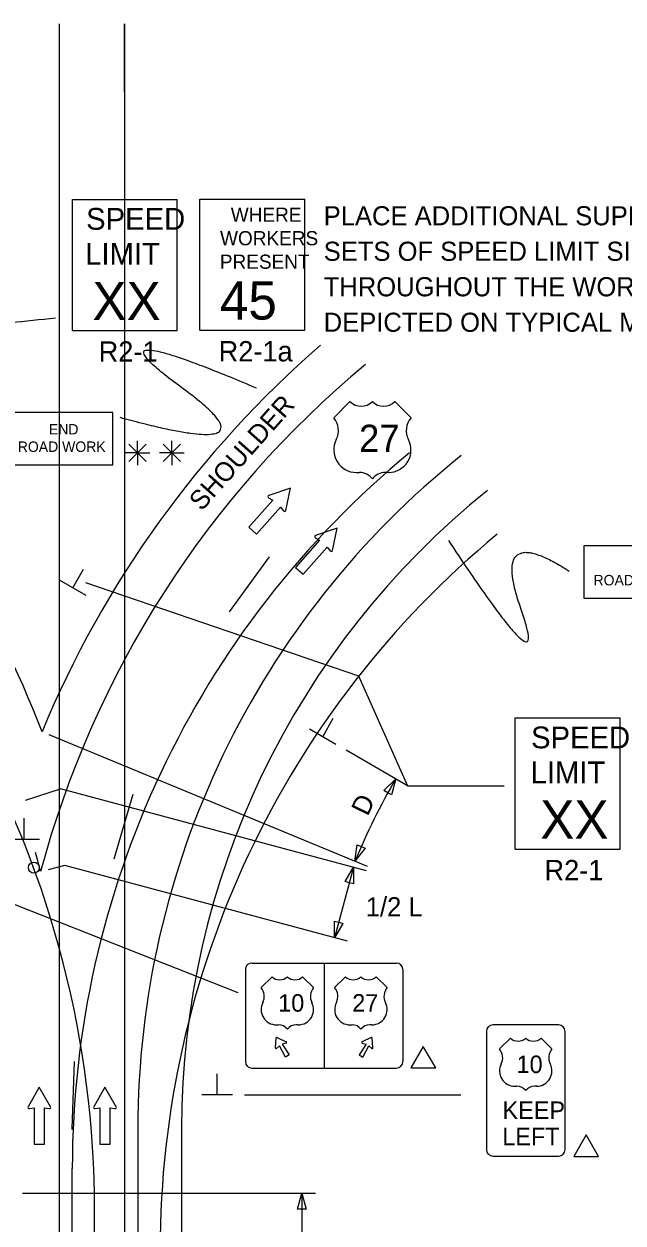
# Model space of a CAD drawing. Extents: x 16731 to 18464, y 5737 to 6974.
# Drawn here: x 16967.8 to 17187.1, y 6535 to 6974.1 of the extents above; entities that cross this region are included whole.
import ezdxf

# ---------------------------------------------------------------- set-up
doc = ezdxf.new("R2010")
doc.units = 0
for name, color, linetype in [('ALI_LEGAL_EX', 7, 'Continuous'), ('MT_SCRATCH_LEVEL_E', 7, 'Continuous'), ('PAVT_EDGE_EX', 7, 'Continuous'), ('TRAFFIC_SIGNS_PR', 7, 'Continuous'), ('TYPICAL_EX', 7, 'Continuous'), ('TYPICAL_TEXT_DIMEN_PR', 7, 'Continuous')]:
    doc.layers.add(name, color=color, linetype=linetype)

msp = doc.modelspace()

# ---------------------------------------------------------------- linework, layer by layer
at = {"layer": 'ALI_LEGAL_EX'}
for p, q in [((16980.68, 6974.12), (16980.68, 6155.98)), ((17004.68, 6974.12), (17004.68, 6155.98)), ((16980.68, 6891.53), (16980.68, 6027.61)), ((17004.68, 6891.53), (17004.68, 6027.61)), ((17007.7, 6691.9), (17000.71, 6668.24)), ((16985.51, 6054.68), (16985.51, 6555.03)), ((16993.65, 6039.29), (16993.65, 6539.64))]:
    msp.add_line(p, q, dxfattribs=at)
for points in [[(17004.68, 6949.12), (17004.68, 6974.12)], [(17043, 6758.79), (17057.75, 6778.98)], [(16985.56, 6569.17), (16985.51, 6569.52), (16986.34, 6594.15)]]:
    msp.add_lwpolyline(points, dxfattribs=at)
for centre, radius, start, end in [((16629.65, 6539.64), 364, 0, 57.2958), ((17325.51, 6555.03), 340, 129.5666, 180), ((17357.65, 6525.15), 340, 129.5666, 180)]:
    msp.add_arc(centre, radius, start, end, dxfattribs=at)
at = {"layer": 'MT_SCRATCH_LEVEL_E'}
for p, q in [((17065.34, 6804.16), (17057.46, 6801.48)), ((17063.63, 6795.99), (17065.34, 6804.16)), ((17058.9, 6799.7), (17050.1, 6789.79)), ((17057.36, 6800.64), (17058.9, 6799.7)), ((17052.89, 6787.3), (17061.7, 6797.21)), ((17061.7, 6797.21), (17062.82, 6795.8)), ((17050.1, 6789.79), (17052.89, 6787.3)), ((17082.42, 6789.5), (17074.54, 6786.82)), ((17080.72, 6781.33), (17082.42, 6789.5)), ((17075.99, 6785.04), (17067.18, 6775.13)), ((17074.45, 6785.99), (17075.99, 6785.04)), ((17069.98, 6772.65), (17078.78, 6782.56)), ((17078.78, 6782.56), (17079.9, 6781.14)), ((17067.18, 6775.13), (17069.98, 6772.65)), ((16973.43, 6584.82), (16969.32, 6577.59)), ((16977.58, 6577.59), (16973.43, 6584.82)), ((16997.48, 6584.82), (16993.37, 6577.59)), ((17001.63, 6577.59), (16997.48, 6584.82)), ((16969.8, 6576.9), (16971.58, 6577.22)), ((16971.58, 6577.22), (16971.58, 6563.96)), ((16975.32, 6563.96), (16975.32, 6577.22)), ((16975.32, 6577.22), (16977.1, 6576.9)), ((16993.85, 6576.9), (16995.63, 6577.22)), ((16995.63, 6577.22), (16995.63, 6563.96)), ((16999.37, 6563.96), (16999.37, 6577.22)), ((16999.37, 6577.22), (17001.15, 6576.9)), ((16971.58, 6563.96), (16975.32, 6563.96)), ((16995.63, 6563.96), (16999.37, 6563.96))]:
    msp.add_line(p, q, dxfattribs=at)
for centre, start, end in [((17057.61, 6801.04), 108.8028, 238.3418), ((17063.18, 6796.09), 218.4141, 348.1511), ((17074.7, 6786.38), 108.8028, 238.3418), ((17080.26, 6781.44), 218.4141, 348.1511), ((16969.73, 6577.36), 150.4248, 279.9638), ((16977.17, 6577.36), 260.0362, 29.7731), ((16993.78, 6577.36), 150.4248, 279.9638), ((17001.22, 6577.36), 260.0362, 29.7731)]:
    msp.add_arc(centre, 0.463, start, end, dxfattribs=at)
at = {"layer": 'PAVT_EDGE_EX'}
for p, q in [((17009.51, 6569.52), (17009.51, 6043.9)), ((17025.51, 6569.52), (17025.51, 6043.9))]:
    msp.add_line(p, q, dxfattribs=at)
for centre, radius, start, end in [((16597.51, 6569.52), 404, 21.0961, 62.1564), ((17325.51, 6569.52), 380, 130.9592, 157.5011), ((17325.51, 6569.52), 364, 129.7293, 165.0045), ((17325.51, 6569.52), 316, 128.7051, 180), ((17325.51, 6569.52), 300, 128.8086, 180), ((16597.51, 6569.52), 388, 14.0482, 15.1223), ((17325.51, 6569.52), 300, 180, 180.00000277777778)]:
    msp.add_arc(centre, radius, start, end, dxfattribs=at)
at = {"layer": 'TRAFFIC_SIGNS_PR'}
for p, q in [((16985.54, 6909.9), (17023.94, 6909.9)), ((16985.54, 6861.9), (16985.54, 6909.9)), ((17023.94, 6861.9), (17023.94, 6909.9)), ((17032.22, 6909.99), (17070.62, 6909.99)), ((17032.22, 6861.99), (17032.22, 6909.99)), ((17070.62, 6861.99), (17070.62, 6909.99)), ((16985.54, 6861.9), (17023.94, 6861.9)), ((17032.22, 6861.99), (17070.62, 6861.99)), ((17147.68, 6719.98), (17186.08, 6719.98)), ((17147.68, 6671.98), (17147.68, 6719.98)), ((17186.08, 6671.98), (17186.08, 6719.98)), ((17147.68, 6671.98), (17186.08, 6671.98)), ((17048.86, 6627.84), (17048.86, 6594.19)), ((17051.26, 6630.24), (17104.13, 6630.24)), ((17077.7, 6630.24), (17077.7, 6591.79)), ((17106.53, 6627.84), (17106.53, 6594.19)), ((17137.08, 6605.16), (17137.08, 6561.91)), ((17163.51, 6607.57), (17139.48, 6607.57)), ((17165.91, 6561.91), (17165.91, 6605.16)), ((17059.85, 6599.15), (17060.14, 6602.78)), ((17060.51, 6602.99), (17063.79, 6601.42)), ((17094.88, 6602.99), (17091.6, 6601.42)), ((17095.54, 6599.15), (17095.25, 6602.78)), ((17051.26, 6591.79), (17104.13, 6591.79)), ((17139.48, 6559.51), (17163.51, 6559.51))]:
    msp.add_line(p, q, dxfattribs=at)
for points in [[(16961.95, 6812.66), (17000.35, 6812.66), (17000.35, 6831.86), (16961.95, 6831.86)], [(17172.71, 6763.79), (17211.11, 6763.79), (17211.11, 6782.99), (17172.71, 6782.99)]]:
    msp.add_lwpolyline(points, close=True, dxfattribs=at)
for points in [[(17063.75, 6600.94), (17062.34, 6600.55), (17064.86, 6596.56), (17063.53, 6595.8), (17061.33, 6599.97), (17060.29, 6598.94)], [(17091.64, 6600.94), (17093.05, 6600.55), (17090.53, 6596.56), (17091.86, 6595.8), (17094.06, 6599.97), (17095.1, 6598.94)]]:
    msp.add_lwpolyline(points, dxfattribs=at)
msp.add_circle((16971.44, 6665.16), 2, dxfattribs=at)
for centre, radius, start, end in [((17051.26, 6627.84), 2.4, 90, 180), ((17051.26, 6627.84), 2.4, 90, 180), ((17104.13, 6627.84), 2.4, 0, 90), ((17139.48, 6605.16), 2.4, 90, 180), ((17163.51, 6605.16), 2.4, 0, 90), ((17060.4, 6602.76), 0.261, 64.4823, 175.5177), ((17063.68, 6601.19), 0.261, 285.9885, 64.4823), ((17091.71, 6601.19), 0.261, 115.5177, 254.0115), ((17094.99, 6602.76), 0.261, 4.4823, 115.5177), ((17060.11, 6599.13), 0.261, 175.5177, 314.0115), ((17095.28, 6599.13), 0.261, 225.9885, 4.4823), ((17051.26, 6594.19), 2.4, 180, 270), ((17104.13, 6594.19), 2.4, 270, 0), ((17139.48, 6561.91), 2.4, 180, 270), ((17163.51, 6561.91), 2.4, 270, 0)]:
    msp.add_arc(centre, radius, start, end, dxfattribs=at)
at = {"layer": 'TYPICAL_EX'}
for p, q in [((17081.21, 6829.94), (17087.1, 6835.84)), ((17109.51, 6829.94), (17103.61, 6835.84)), ((17089.45, 6809.88), (17090.63, 6809.88)), ((17101.26, 6809.88), (17100.08, 6809.88)), ((17054.62, 6621.23), (17058.62, 6625.23)), ((17073.84, 6621.23), (17069.84, 6625.23)), ((17081.55, 6621.23), (17085.55, 6625.23)), ((17100.77, 6621.23), (17096.77, 6625.23)), ((17060.22, 6607.6), (17061.02, 6607.6)), ((17068.24, 6607.6), (17067.44, 6607.6)), ((17087.15, 6607.6), (17087.95, 6607.6)), ((17095.17, 6607.6), (17094.37, 6607.6)), ((17141.88, 6598.76), (17145.89, 6602.76)), ((17161.11, 6598.76), (17157.1, 6602.76)), ((17147.48, 6585.13), (17148.28, 6585.13)), ((17155.5, 6585.13), (17154.7, 6585.13))]:
    msp.add_line(p, q, dxfattribs=at)
for centre, radius, start, end in [((17091.23, 6840.13), 5.96, 226.1404, 313.8596), ((17099.48, 6840.13), 5.96, 226.1404, 313.8596), ((17075.62, 6825.22), 7.31, 333.0977, 40.1936), ((17115.09, 6825.22), 7.31, 139.8064, 206.9023), ((17089.47, 6818.13), 8.24, 152.6698, 269.9013), ((17101.25, 6818.13), 8.24, 270.0987, 27.3302), ((17090.65, 6803.98), 5.91, 37.1038, 90.1385), ((17100.07, 6803.98), 5.91, 89.8615, 142.8962), ((17061.43, 6628.15), 4.05, 226.1404, 313.8596), ((17067.03, 6628.15), 4.05, 226.1404, 313.8596), ((17088.36, 6628.15), 4.05, 226.1404, 313.8596), ((17093.96, 6628.15), 4.05, 226.1404, 313.8596), ((17050.82, 6618.02), 4.97, 333.0977, 40.1936), ((17077.64, 6618.02), 4.97, 139.8064, 206.9023), ((17077.75, 6618.02), 4.97, 333.0977, 40.1936), ((17104.57, 6618.02), 4.97, 139.8064, 206.9023), ((17060.23, 6613.2), 5.6, 152.6698, 269.9013), ((17068.23, 6613.2), 5.6, 270.0987, 27.3302), ((17087.16, 6613.2), 5.6, 152.6698, 269.9013), ((17095.16, 6613.2), 5.6, 270.0987, 27.3302), ((17061.03, 6603.59), 4.01, 37.1038, 90.1385), ((17067.43, 6603.59), 4.01, 89.8615, 142.8962), ((17087.96, 6603.59), 4.01, 37.1038, 90.1385), ((17094.36, 6603.59), 4.01, 89.8615, 142.8962), ((17148.69, 6605.68), 4.05, 226.1404, 313.8596), ((17154.3, 6605.68), 4.05, 226.1404, 313.8596), ((17138.09, 6595.55), 4.97, 333.0977, 40.1936), ((17164.9, 6595.55), 4.97, 139.8064, 206.9023), ((17147.49, 6590.73), 5.6, 152.6698, 269.9013), ((17155.49, 6590.73), 5.6, 270.0987, 27.3302), ((17148.29, 6581.11), 4.01, 37.1038, 90.1385), ((17154.69, 6581.11), 4.01, 89.8615, 142.8962)]:
    msp.add_arc(centre, radius, start, end, dxfattribs=at)
at = {"layer": 'TYPICAL_TEXT_DIMEN_PR'}
for p, q in [((17012.56, 6820.22), (17006.18, 6813.84)), ((17006.19, 6820.22), (17012.56, 6813.84)), ((17009.37, 6817.03), (17009.37, 6821.49)), ((17018.74, 6820.22), (17025.12, 6813.84)), ((17025.12, 6820.22), (17018.74, 6813.84)), ((17021.93, 6817.03), (17021.93, 6821.49)), ((17009.37, 6817.03), (17004.84, 6817.03)), ((17009.37, 6817.03), (17012.56, 6817.03)), ((17009.37, 6817.03), (17013.85, 6817.03)), ((17009.37, 6817.03), (17009.37, 6812.53)), ((17021.93, 6817.03), (17017.4, 6817.03)), ((17021.93, 6817.03), (17025.12, 6817.03)), ((17021.93, 6817.03), (17026.41, 6817.03)), ((17021.93, 6817.03), (17021.93, 6812.53)), ((16985.67, 6767.67), (16989.56, 6774.42)), ((16990.54, 6764.86), (16980.8, 6770.49)), ((16990.33, 6769.61), (17090.24, 6735.43)), ((17090.24, 6735.43), (17108.22, 6695.16)), ((17077.17, 6713.12), (17081.06, 6719.86)), ((17093.61, 6665.56), (16977.03, 6713.85)), ((17082.04, 6710.31), (17072.29, 6715.93)), ((17108.22, 6695.16), (17085.71, 6708.17)), ((17099.6, 6693.37), (17103.89, 6697.66)), ((17103.89, 6697.66), (17102.32, 6691.8)), ((16968.4, 6689.84), (16981.21, 6693.99)), ((17093.19, 6664), (16981.21, 6693.99)), ((17100.96, 6692.59), (17099.6, 6693.37)), ((17102.32, 6691.8), (17100.96, 6692.59)), ((17108.22, 6695.16), (17143.57, 6695.16)), ((16967.87, 6675.48), (16967.87, 6683.27)), ((16973.49, 6675.48), (16962.24, 6675.48)), ((17088.99, 6667.48), (17089.79, 6673.49)), ((17092.69, 6672.29), (17088.99, 6667.48)), ((17089.79, 6673.49), (17091.24, 6672.89)), ((17091.24, 6672.89), (17092.69, 6672.29)), ((16969.74, 6666.21), (16969.74, 6666.2)), ((16982.82, 6665.93), (16976.66, 6664.39)), ((17086.29, 6638.21), (16982.82, 6665.93)), ((17088.41, 6665.28), (17081.5, 6639.5)), ((17085.37, 6660.03), (17088.41, 6665.28)), ((17088.41, 6665.28), (17088.41, 6659.21)), ((17086.89, 6659.62), (17085.37, 6660.03)), ((17088.41, 6659.21), (17086.89, 6659.62)), ((16964.45, 6651.69), (17046.11, 6619.48)), ((17081.5, 6639.5), (17081.5, 6645.57)), ((17081.5, 6645.57), (17083.02, 6645.16)), ((17084.53, 6644.75), (17081.5, 6639.5)), ((17083.02, 6645.16), (17084.53, 6644.75)), ((17038.53, 6581.91), (17038.53, 6589.7)), ((17044.15, 6581.91), (17032.9, 6581.91)), ((17048.51, 6581.91), (17127.7, 6581.91)), ((16967.28, 6545.96), (17074.51, 6545.96)), ((17067.94, 6540.1), (17069.51, 6545.96)), ((17069.51, 6545.96), (17069.51, 6513.85)), ((17069.51, 6545.96), (17071.08, 6540.1)), ((17069.51, 6540.1), (17067.94, 6540.1)), ((17071.08, 6540.1), (17069.51, 6540.1))]:
    msp.add_line(p, q, dxfattribs=at)
for points in [[(17114.01, 6599.66), (17109.48, 6591.83), (17118.53, 6591.83)], [(17173.58, 6567.27), (17169.06, 6559.44), (17178.11, 6559.44)]]:
    msp.add_lwpolyline(points, close=True, dxfattribs=at)
msp.add_arc((17325.51, 6569.52), 256, 149.9625, 157.5013, dxfattribs=at)
for points in [[(16914.62, 6827.39), (16976.79, 6834.13), (16886.34, 6857.55), (16979.34, 6866.49)], [(17002.93, 6830.08), (17063.23, 6813.47), (16987.75, 6868.54), (17052.82, 6840.87)], [(17123.19, 6785.02), (17161.42, 6726.85), (17138.21, 6792.55), (17167.37, 6773.79)]]:
    msp.add_open_spline(points, degree=2, dxfattribs=at)

# ---------------------------------------------------------------- texts
at = {"layer": 'TRAFFIC_SIGNS_PR'}
for s, height, p in [('PLACE ADDITIONAL SUPPLEMENTAL', 7, (17077.54, 6900.39)), ('SPEED', 8, (16990.57, 6898.76)), ('WHERE', 5.2, (17043.53, 6901.67)), ('WORKERS', 5.2, (17039.6, 6893.07)), ('LIMIT', 8, (16990.24, 6885.96)), ('SETS OF SPEED LIMIT SIGNS', 7, (17077.54, 6887.39)), ('PRESENT', 5.2, (17039.53, 6884.47)), ('THROUGHOUT THE WORK AREA AS', 7, (17077.54, 6874.39)), ('XX', 14.031, (16992.85, 6865.66)), ('45', 14.031, (17039.52, 6865.85)), ('DEPICTED ON TYPICAL M0100a.', 7, (17077.54, 6861.39)), ('R2-1', 7.44, (16995.15, 6850.46)), ('R2-1a', 7.44, (17039.07, 6850.55)), ('END', 3.831, (16976.95, 6823.79)), ('ROAD WORK', 3.831, (16965.56, 6817.4)), ('ROAD WORK', 3.831, (17176.32, 6768.53)), ('SPEED', 8, (17153.45, 6708.85)), ('LIMIT', 8, (17153.28, 6696.05)), ('XX', 14.031, (17156.79, 6675.74)), ('R2-1', 7.44, (17158.36, 6660.54)), ('10', 6.408, (17060.89, 6612.42)), ('27', 6.408, (17087.99, 6612.42)), ('10', 6.408, (17148.15, 6589.94)), ('KEEP', 6.408, (17143.02, 6573.12)), ('LEFT', 6.408, (17142.93, 6563.51))]:
    msp.add_text(s, height=height, dxfattribs=at).set_placement(p)
at = {"layer": 'TYPICAL_EX'}
msp.add_text('27', height=10, dxfattribs=at).set_placement((17090.47, 6817.37))
at = {"layer": 'TYPICAL_TEXT_DIMEN_PR'}
for s, rotation, p in [('SHOULDER', 48.378, (17032.86, 6795.46)), ('D', 63.7334, (17093.58, 6683.72))]:
    msp.add_text(s, height=7, rotation=rotation, dxfattribs=at).set_placement(p)
msp.add_text('1/2 L', height=7, dxfattribs=at).set_placement((17092.94, 6647.35))

doc.saveas('drawing.dxf')
